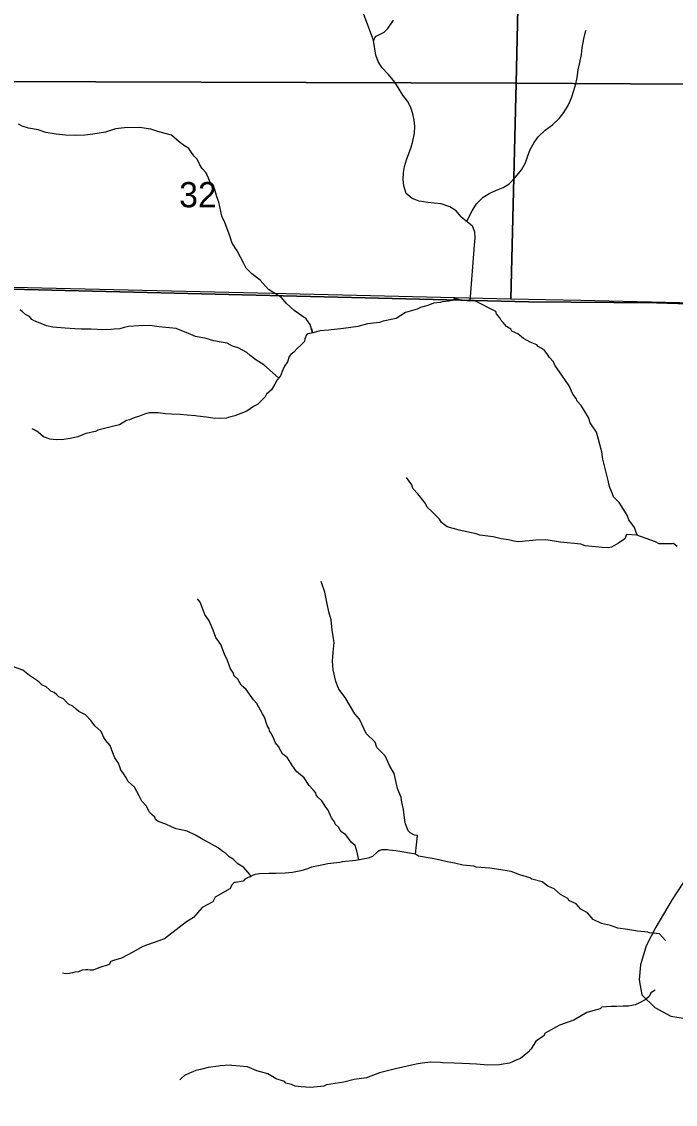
# Model space of a CAD drawing. Extents: x -10 to 158, y 8 to 33.
# Drawn here: x -8.573 to -7.489, y 17.013 to 18.808 of the extents above; entities that cross this region are included whole.
import ezdxf

# ---------------------------------------------------------------- set-up
doc = ezdxf.new("R2010")
doc.units = 0
for name, color, linetype in [('GM_X_Corporation', 7, 'Continuous'), ('GM_X_Minor_River', 7, 'Continuous'), ('GM_X_Rail_Line', 7, 'Continuous'), ('GM_X_Section_Text', 7, 'Continuous')]:
    doc.layers.add(name, color=color, linetype=linetype)

msp = doc.modelspace()

# ---------------------------------------------------------------- linework, layer by layer
at = {"layer": 'GM_X_Corporation'}
for points in [[(-9.7914, 22.7162), (-9.7914, 18.392), (-9.6242, 18.3881), (-9.0027, 18.3743), (-8.9838, 18.3739), (-8.93, 18.3728), (-7.7325, 18.3437), (-7.5205, 18.3416), (-6.9708, 18.3249), (-6.1191, 18.3027), (-6.0053, 18.2999), (-5.6789, 18.2975), (-5.6625, 19.6663)], [(-5.6625, 19.6663), (-5.6789, 18.2975), (-6.0053, 18.2999), (-6.1191, 18.3027), (-6.9708, 18.3249), (-7.5205, 18.3416), (-7.7325, 18.3437), (-8.93, 18.3728), (-8.9838, 18.3739), (-9.0027, 18.3743), (-9.6242, 18.3881), (-9.6444, 17.5212), (-9.6604, 16.9971), (-9.6851, 16.2018), (-9.6914, 16.0183), (-3.6338, 16.0183), (-3.6311, 16.2195), (-3.6167, 17.6595), (-3.6057, 18.5118), (-3.613, 18.695), (-3.6159, 19.0246)]]:
    msp.add_lwpolyline(points, dxfattribs=at)
for points in [[(-8.7894, 19.7325), (-7.7305, 19.7203), (-7.753, 18.706), (-8.7982, 18.7092)], [(-7.7305, 19.7203), (-6.6993, 19.7075), (-6.7094, 18.6997), (-7.753, 18.706)], [(-8.7982, 18.7092), (-7.753, 18.706), (-7.7617, 18.3482), (-8.1572, 18.3575), (-8.6592, 18.3688), (-8.8015, 18.3735)], [(-7.753, 18.706), (-6.7094, 18.6997), (-6.7106, 18.3234), (-7.6461, 18.3457), (-7.7617, 18.3482)]]:
    msp.add_lwpolyline(points, close=True, dxfattribs=at)
at = {"layer": 'GM_X_Minor_River'}
for points in [[(-8.0064, 18.822), (-7.9893, 18.7763), (-7.9864, 18.7832), (-7.9717, 18.7906), (-7.9658, 18.7968), (-7.9561, 18.8106)], [(-7.8347, 18.4772), (-7.8261, 18.4944), (-7.8189, 18.5059), (-7.8079, 18.5169), (-7.7966, 18.5237), (-7.7854, 18.5287), (-7.7746, 18.5332), (-7.7649, 18.5386), (-7.7539, 18.55), (-7.7443, 18.5625), (-7.7378, 18.5741), (-7.7336, 18.5857), (-7.7298, 18.5962), (-7.7234, 18.6074), (-7.7166, 18.617), (-7.7048, 18.628), (-7.6927, 18.6367), (-7.6817, 18.6473), (-7.6741, 18.6573), (-7.6661, 18.6703), (-7.6611, 18.6819), (-7.6573, 18.6936), (-7.6542, 18.7049), (-7.6519, 18.7154), (-7.65, 18.7279), (-7.6477, 18.74), (-7.6449, 18.7536), (-7.6434, 18.7645), (-7.641, 18.7793), (-7.6383, 18.7909), (-7.637, 18.7939)], [(-7.8443, 18.4844), (-7.8527, 18.4946), (-7.8627, 18.501), (-7.8774, 18.5061), (-7.8887, 18.5072), (-7.8997, 18.5084), (-7.9137, 18.5104), (-7.9253, 18.515), (-7.9353, 18.5229), (-7.9394, 18.536), (-7.9402, 18.5463), (-7.9398, 18.5581), (-7.9383, 18.5679), (-7.9349, 18.5788), (-7.9307, 18.5893), (-7.9269, 18.5998), (-7.9243, 18.6099), (-7.9215, 18.6231), (-7.9212, 18.6342), (-7.9223, 18.6448), (-7.9242, 18.6552), (-7.9277, 18.6655), (-7.9334, 18.676), (-7.9406, 18.6861), (-7.9471, 18.6962), (-7.9543, 18.7079), (-7.9645, 18.7204), (-7.9755, 18.7322), (-7.982, 18.7419), (-7.9858, 18.7523), (-7.9896, 18.7768)], [(-8.0923, 18.2993), (-8.0908, 18.2919), (-8.0943, 18.3062), (-8.1009, 18.3152), (-8.1209, 18.3293), (-8.1344, 18.3412), (-8.1418, 18.3506), (-8.1636, 18.364), (-8.1772, 18.3797), (-8.1914, 18.3897), (-8.2003, 18.3991), (-8.2043, 18.407), (-8.2152, 18.4281), (-8.2238, 18.4405), (-8.227, 18.4515), (-8.2358, 18.4753), (-8.2409, 18.4858), (-8.2426, 18.4934), (-8.2459, 18.5089), (-8.2491, 18.5173), (-8.2527, 18.5297), (-8.2578, 18.5376), (-8.2613, 18.5448), (-8.2668, 18.5573), (-8.2734, 18.5644), (-8.2773, 18.5708), (-8.2816, 18.5798), (-8.287, 18.5851), (-8.2902, 18.5896), (-8.2956, 18.5978), (-8.3044, 18.6034), (-8.3118, 18.609), (-8.3245, 18.6198), (-8.3451, 18.6256), (-8.3588, 18.6295), (-8.3775, 18.6323), (-8.4021, 18.6319), (-8.4169, 18.6301), (-8.4339, 18.6249), (-8.4547, 18.6212), (-8.468, 18.6198), (-8.4835, 18.6192), (-8.5002, 18.6197), (-8.5097, 18.6207), (-8.5154, 18.6217), (-8.5326, 18.6241), (-8.5452, 18.6285), (-8.5616, 18.6316), (-8.5719, 18.6349), (-8.578, 18.6378)], [(-7.8443, 18.4844), (-7.8258, 18.47), (-7.822, 18.4593), (-7.8216, 18.4494), (-7.8228, 18.4376), (-7.83, 18.3445)], [(-7.7868, 18.3273), (-7.8217, 18.3454), (-7.83, 18.3445), (-7.8471, 18.3469), (-7.8525, 18.3483), (-7.8555, 18.3483), (-7.8589, 18.346), (-7.8638, 18.3447), (-7.8755, 18.3434), (-7.8782, 18.3426), (-7.8899, 18.3413), (-7.8994, 18.3373), (-7.9118, 18.3341), (-7.9171, 18.3314), (-7.9364, 18.3261), (-7.9521, 18.316), (-7.9737, 18.3115), (-7.9794, 18.3095), (-7.9994, 18.3073), (-8.0153, 18.3028), (-8.0312, 18.3003), (-8.0437, 18.2986), (-8.0596, 18.2972), (-8.0634, 18.2968), (-8.0782, 18.2954), (-8.0895, 18.2922), (-8.0978, 18.2905), (-8.1005, 18.289), (-8.1034, 18.2821), (-8.1041, 18.2775), (-8.1089, 18.2729), (-8.116, 18.2659), (-8.1216, 18.2601), (-8.1265, 18.2562), (-8.1291, 18.2528), (-8.1323, 18.244), (-8.1368, 18.2371), (-8.1397, 18.231), (-8.1437, 18.221), (-8.1493, 18.2141), (-8.153, 18.2072), (-8.1585, 18.1976), (-8.1667, 18.1906), (-8.1689, 18.186), (-8.1816, 18.1733), (-8.1884, 18.1698), (-8.1996, 18.162), (-8.2196, 18.1545), (-8.2302, 18.152), (-8.2329, 18.1508), (-8.2427, 18.1503), (-8.256, 18.1509), (-8.267, 18.1526), (-8.2811, 18.1539), (-8.2845, 18.1546), (-8.2982, 18.1555), (-8.31, 18.1565), (-8.3245, 18.1574), (-8.334, 18.158), (-8.3465, 18.1597), (-8.3613, 18.1595), (-8.3689, 18.1574), (-8.3775, 18.1539), (-8.3862, 18.1511), (-8.39, 18.1495), (-8.3941, 18.1479), (-8.3987, 18.1467), (-8.4107, 18.1397), (-8.4179, 18.138), (-8.4311, 18.1344), (-8.4466, 18.1308), (-8.4504, 18.1284), (-8.4662, 18.1251), (-8.4798, 18.1196), (-8.4923, 18.1171), (-8.5029, 18.1151), (-8.515, 18.1149), (-8.5261, 18.1158), (-8.5314, 18.118), (-8.5364, 18.1195), (-8.5453, 18.1277), (-8.5518, 18.1314), (-8.5552, 18.1332)], [(-8.1467, 18.2174), (-8.171, 18.2392), (-8.1844, 18.2474), (-8.194, 18.2544), (-8.1994, 18.2593), (-8.2136, 18.267), (-8.2231, 18.2703), (-8.232, 18.2751), (-8.2453, 18.2772), (-8.2544, 18.2789), (-8.267, 18.2825), (-8.2845, 18.2861), (-8.2964, 18.2908), (-8.3166, 18.2992), (-8.3448, 18.3022), (-8.36, 18.3042), (-8.3782, 18.3036), (-8.3957, 18.3025), (-8.4029, 18.3009), (-8.41, 18.2989), (-8.4191, 18.298), (-8.4241, 18.2975), (-8.44, 18.2973), (-8.4468, 18.2976), (-8.4575, 18.2982), (-8.4738, 18.2983), (-8.4848, 18.2985), (-8.5004, 18.3001), (-8.5209, 18.3013), (-8.5316, 18.3035), (-8.5419, 18.3082), (-8.5518, 18.3119), (-8.5557, 18.3145), (-8.5596, 18.319), (-8.5661, 18.3227), (-8.5715, 18.3271), (-8.5753, 18.3301)], [(-7.5521, 17.9564), (-7.5539, 17.9613), (-7.5567, 17.9692), (-7.5664, 17.982), (-7.5692, 17.9899), (-7.5824, 18.011), (-7.5917, 18.02), (-7.5933, 18.0253), (-7.5977, 18.0358), (-7.5993, 18.0411), (-7.5997, 18.0453), (-7.605, 18.065), (-7.6095, 18.0828), (-7.6108, 18.0949), (-7.6201, 18.1274), (-7.6306, 18.1428), (-7.6331, 18.1519), (-7.6452, 18.1715), (-7.6521, 18.1786), (-7.6537, 18.1831), (-7.6592, 18.1903), (-7.6651, 18.2042), (-7.6713, 18.2129), (-7.6889, 18.2388), (-7.6909, 18.2441), (-7.6978, 18.2512), (-7.7013, 18.2561), (-7.7068, 18.264), (-7.7163, 18.2692), (-7.7187, 18.2722), (-7.7298, 18.2769), (-7.7409, 18.2828), (-7.7501, 18.2907), (-7.7601, 18.2951), (-7.762, 18.2981), (-7.7693, 18.3025), (-7.7744, 18.3093), (-7.7778, 18.3123), (-7.7802, 18.3168), (-7.7856, 18.3239), (-7.7868, 18.3273)], [(-7.4859, 17.938), (-7.492, 17.9429), (-7.4947, 17.9421), (-7.516, 17.9425), (-7.5221, 17.9454), (-7.553, 17.9567), (-7.5701, 17.9576), (-7.573, 17.9507), (-7.5835, 17.9437), (-7.5911, 17.939), (-7.5952, 17.9367), (-7.5997, 17.9359), (-7.6104, 17.9365), (-7.6385, 17.939), (-7.6461, 17.9416), (-7.6796, 17.9452), (-7.704, 17.949), (-7.7207, 17.9484), (-7.7256, 17.9479), (-7.7381, 17.9466), (-7.743, 17.9461), (-7.7491, 17.9457), (-7.7571, 17.9467), (-7.7655, 17.9488), (-7.7777, 17.9509), (-7.7914, 17.9541), (-7.8131, 17.9568), (-7.8192, 17.959), (-7.8477, 17.965), (-7.8676, 17.9708), (-7.8768, 17.9778), (-7.8803, 17.9831), (-7.8915, 17.9951), (-7.9008, 18.0029), (-7.9032, 18.0094), (-7.916, 18.0251), (-7.9241, 18.0341), (-7.9261, 18.0402), (-7.935, 18.0522)], [(-7.9197, 17.4277), (-7.9168, 17.4589), (-7.9218, 17.4596), (-7.9287, 17.4633), (-7.9318, 17.4666), (-7.9365, 17.478), (-7.9378, 17.4836), (-7.94, 17.5018), (-7.9428, 17.514), (-7.9434, 17.5219), (-7.9497, 17.537), (-7.9554, 17.5616), (-7.9625, 17.5737), (-7.9704, 17.5907), (-7.9839, 17.6049), (-7.9867, 17.6136), (-8.0014, 17.6282), (-8.0128, 17.6516), (-8.0202, 17.6606), (-8.0362, 17.6877), (-8.0471, 17.7016), (-8.0518, 17.7144), (-8.0563, 17.7337), (-8.0574, 17.7481), (-8.0561, 17.7622), (-8.0548, 17.779), (-8.0562, 17.7888), (-8.0579, 17.7991), (-8.0597, 17.8161), (-8.0637, 17.8294), (-8.0662, 17.843), (-8.0699, 17.862), (-8.0763, 17.8801)], [(-8.0139, 17.4184), (-8.017, 17.4334), (-8.019, 17.4383), (-8.0198, 17.4424), (-8.0267, 17.448), (-8.0306, 17.4533), (-8.0361, 17.4604), (-8.0422, 17.4645), (-8.0446, 17.4679), (-8.0477, 17.4728), (-8.0531, 17.4776), (-8.0539, 17.4814), (-8.0593, 17.4882), (-8.0649, 17.501), (-8.0684, 17.5059), (-8.0754, 17.5161), (-8.0816, 17.5224), (-8.0847, 17.5262), (-8.0855, 17.5303), (-8.0894, 17.5348), (-8.0963, 17.5416), (-8.1045, 17.5547), (-8.1172, 17.5648), (-8.1238, 17.5746), (-8.132, 17.5874), (-8.1405, 17.5941), (-8.1432, 17.5993), (-8.1472, 17.6065), (-8.1522, 17.6125), (-8.1546, 17.6193), (-8.1585, 17.6276), (-8.162, 17.6321), (-8.1625, 17.6355), (-8.166, 17.6412), (-8.17, 17.6548), (-8.1735, 17.6608), (-8.1829, 17.6774), (-8.1883, 17.6838), (-8.2004, 17.7007), (-8.2089, 17.7081), (-8.2144, 17.7179), (-8.2209, 17.7239), (-8.2218, 17.7281), (-8.2268, 17.7352), (-8.2316, 17.7492), (-8.2367, 17.7594), (-8.2423, 17.7753), (-8.2509, 17.7873), (-8.2553, 17.7994), (-8.262, 17.8148), (-8.269, 17.825), (-8.2726, 17.8341), (-8.2769, 17.8458), (-8.2812, 17.851)], [(-8.1938, 17.3904), (-8.1924, 17.3911), (-8.1944, 17.3941), (-8.2044, 17.4057), (-8.2144, 17.412), (-8.2221, 17.4199), (-8.229, 17.4236), (-8.2341, 17.4288), (-8.241, 17.4333), (-8.2468, 17.4385), (-8.2751, 17.454), (-8.2847, 17.4592), (-8.2985, 17.4662), (-8.3168, 17.4701), (-8.3244, 17.473), (-8.3336, 17.4774), (-8.3462, 17.4818), (-8.3508, 17.4855), (-8.352, 17.4893), (-8.3559, 17.4926), (-8.3613, 17.4979), (-8.366, 17.5077), (-8.3737, 17.5155), (-8.3781, 17.5246), (-8.3855, 17.5389), (-8.3959, 17.5482), (-8.4002, 17.5558), (-8.4049, 17.5633), (-8.4084, 17.5671), (-8.4096, 17.5708), (-8.4124, 17.5788), (-8.4183, 17.5874), (-8.4214, 17.5961), (-8.4262, 17.6082), (-8.4332, 17.6161), (-8.4363, 17.6213), (-8.441, 17.6315), (-8.4514, 17.6405), (-8.4576, 17.6487), (-8.4666, 17.6589), (-8.4777, 17.6644), (-8.4823, 17.6685), (-8.4877, 17.6734), (-8.495, 17.6767), (-8.4984, 17.68), (-8.5035, 17.6853), (-8.5111, 17.6889), (-8.5146, 17.6919), (-8.5188, 17.6957), (-8.5242, 17.6982), (-8.5269, 17.7009), (-8.5319, 17.7053), (-8.5392, 17.7086), (-8.5438, 17.7128), (-8.5465, 17.7154), (-8.5599, 17.7243), (-8.5707, 17.7328), (-8.586, 17.7387)], [(-7.5054, 17.2848), (-7.5154, 17.2957), (-7.5318, 17.2973), (-7.5348, 17.2984), (-7.552, 17.3001), (-7.5683, 17.3032), (-7.5847, 17.3053), (-7.5969, 17.3096), (-7.6118, 17.3128), (-7.6252, 17.3194), (-7.6349, 17.3307), (-7.6456, 17.3366), (-7.6537, 17.3456), (-7.6656, 17.3511), (-7.6675, 17.3545), (-7.6794, 17.3612), (-7.6902, 17.3705), (-7.7005, 17.3749), (-7.7101, 17.382), (-7.7273, 17.3862), (-7.7304, 17.3889), (-7.7472, 17.3935), (-7.7613, 17.399), (-7.7712, 17.4008), (-7.7967, 17.4045), (-7.8195, 17.4065), (-7.823, 17.4079), (-7.8412, 17.4099), (-7.8553, 17.4131), (-7.8648, 17.4145), (-7.8892, 17.4202), (-7.9147, 17.4247), (-7.9197, 17.4277), (-7.9525, 17.4336), (-7.9635, 17.4346), (-7.9662, 17.4353), (-7.976, 17.4351), (-7.9802, 17.4336), (-7.9828, 17.432), (-7.991, 17.4239), (-7.9982, 17.4215), (-8.019, 17.4174), (-8.0414, 17.4151), (-8.0451, 17.4139), (-8.0652, 17.4117), (-8.0807, 17.4084), (-8.0921, 17.4063), (-8.0989, 17.4036), (-8.1098, 17.4004), (-8.1238, 17.3975), (-8.1359, 17.3965), (-8.1507, 17.3959), (-8.1629, 17.3957), (-8.1784, 17.3951), (-8.1864, 17.3942), (-8.1898, 17.3923), (-8.2026, 17.3864), (-8.2056, 17.3833), (-8.2181, 17.3812), (-8.2207, 17.3808), (-8.2237, 17.3777), (-8.2274, 17.3704), (-8.2518, 17.3567), (-8.2558, 17.349), (-8.2735, 17.3393), (-8.288, 17.3227), (-8.2997, 17.316), (-8.336, 17.2873), (-8.3719, 17.275), (-8.3884, 17.2652), (-8.4072, 17.2554), (-8.4204, 17.2518), (-8.425, 17.2502), (-8.4279, 17.2452), (-8.4445, 17.2393), (-8.4539, 17.2357), (-8.4593, 17.2356), (-8.4631, 17.2359), (-8.4661, 17.2359), (-8.4722, 17.2354), (-8.4786, 17.233), (-8.4843, 17.2322), (-8.4884, 17.231), (-8.4941, 17.2301), (-8.5002, 17.2297), (-8.5051, 17.2307)], [(-7.5225, 17.2026), (-7.5297, 17.1978), (-7.5326, 17.1917), (-7.539, 17.1863), (-7.5495, 17.1808), (-7.5555, 17.178), (-7.5669, 17.1759), (-7.5756, 17.1762), (-7.5866, 17.1756), (-7.5957, 17.1755), (-7.6109, 17.1741), (-7.6139, 17.1718), (-7.6358, 17.1657), (-7.6576, 17.1529), (-7.681, 17.1445), (-7.7047, 17.1312), (-7.7076, 17.1262), (-7.7204, 17.118), (-7.7282, 17.105), (-7.7337, 17.0992), (-7.7461, 17.0891), (-7.7518, 17.0868), (-7.7638, 17.0816), (-7.7778, 17.0791), (-7.7808, 17.0787), (-7.8002, 17.0784), (-7.8188, 17.08), (-7.8306, 17.0806), (-7.8557, 17.0813), (-7.8754, 17.0818), (-7.8785, 17.0825), (-7.8948, 17.083), (-7.9088, 17.0812), (-7.919, 17.0796), (-7.9406, 17.0751), (-7.9531, 17.0718), (-7.9795, 17.0657), (-8.001, 17.057), (-8.0215, 17.0544), (-8.0389, 17.0499), (-8.0676, 17.0453), (-8.0718, 17.0433), (-8.0941, 17.0411), (-8.1093, 17.042), (-8.1192, 17.0434), (-8.1254, 17.0463), (-8.1349, 17.0484), (-8.1368, 17.0511), (-8.1506, 17.0554), (-8.1648, 17.0639), (-8.1827, 17.069), (-8.1984, 17.0752), (-8.2242, 17.0774), (-8.2273, 17.0781), (-8.2439, 17.0771), (-8.2466, 17.0763), (-8.2633, 17.0745), (-8.2761, 17.0709), (-8.2841, 17.0693), (-8.2957, 17.0645), (-8.3025, 17.061), (-8.3078, 17.0567), (-8.3105, 17.0539)]]:
    msp.add_lwpolyline(points, dxfattribs=at)
at = {"layer": 'GM_X_Rail_Line'}
msp.add_lwpolyline([(-7.4672, 17.3944), (-7.4943, 17.3529), (-7.5214, 17.3069), (-7.5374, 17.2757), (-7.5468, 17.2442), (-7.5493, 17.2198), (-7.5449, 17.1947), (-7.5232, 17.1739), (-7.4966, 17.1596), (-7.4729, 17.1553)], dxfattribs=at)

# ---------------------------------------------------------------- texts
at = {"layer": 'GM_X_Section_Text'}
msp.add_text('32', height=0.04186, rotation=0, dxfattribs=at).set_placement((-8.3116, 18.5002))

doc.saveas('drawing.dxf')
